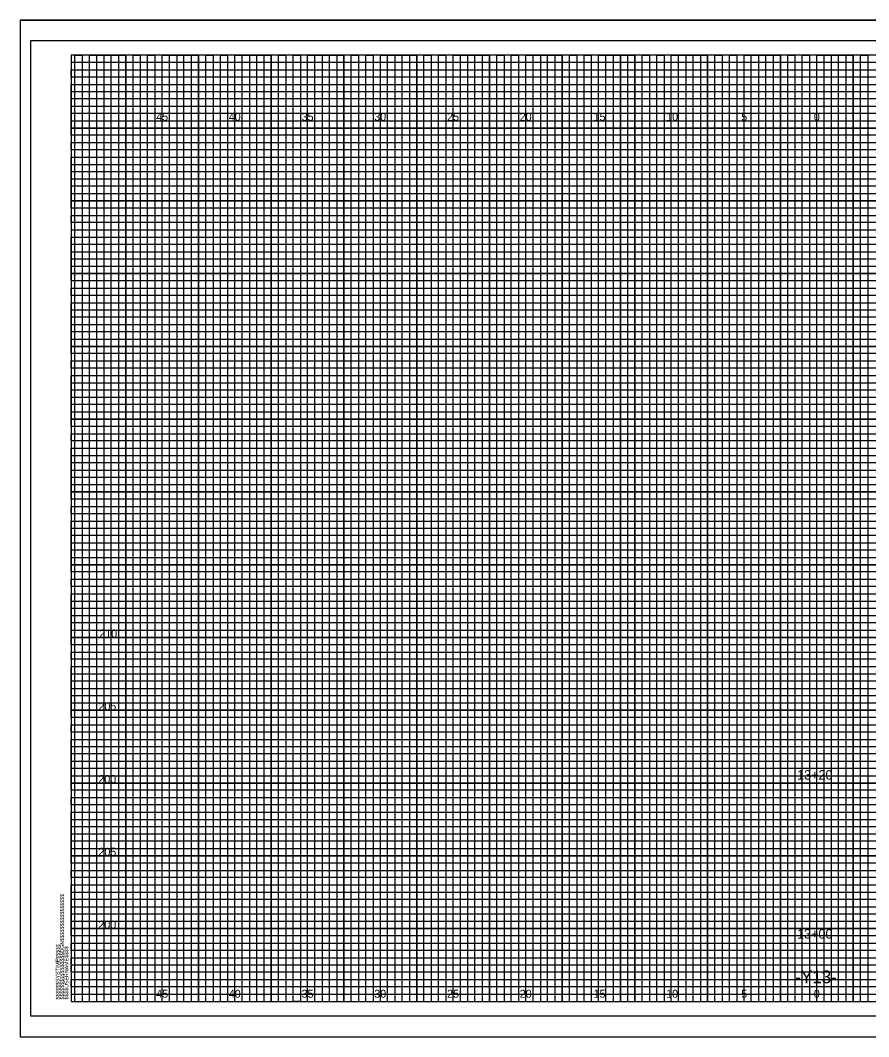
# Model space of a CAD drawing. Extents: x -4 to 103, y -2 to 209.
# Drawn here: x -3.5 to 54.8, y 139.2 to 209.1 of the extents above; entities that cross this region are included whole.
import ezdxf

# ---------------------------------------------------------------- set-up
doc = ezdxf.new("R2010")
doc.units = 0
for name, color, linetype in [('Exist XS Ground Line', 7, 'Continuous'), ('Old_Level_10', 7, 'Continuous'), ('Old_Level_16', 7, 'Continuous'), ('Old_Level_3', 7, 'Continuous'), ('Old_Level_5', 7, 'Continuous'), ('Old_Level_8', 7, 'Continuous'), ('Prop XS Finish Grade Earthwork', 7, 'Continuous'), ('Prop XS Finish Grade Pavement', 7, 'Continuous'), ('Prop XS Pvmt Edge Slope', 7, 'Continuous'), ('Prop XS SE Text', 7, 'Continuous'), ('Prop XS Suitable Common Exc Shape', 7, 'Continuous')]:
    doc.layers.add(name, color=color, linetype=linetype)

msp = doc.modelspace()

# ---------------------------------------------------------------- linework, layer by layer
at = {"layer": 'Exist XS Ground Line'}
msp.add_lwpolyline([(103, 207.65), (-2.8, 207.65), (-2.8, 140.65), (103, 140.65)], close=True, dxfattribs=at)
at = {"layer": 'Old_Level_10'}
for p, q in [((1.25, 141.65), (1.25, 206.65)), ((3.75, 141.65), (3.75, 206.65)), ((6.25, 141.65), (6.25, 206.65)), ((8.75, 141.65), (8.75, 206.65)), ((11.25, 141.65), (11.25, 206.65)), ((13.75, 141.65), (13.75, 206.65)), ((16.25, 141.65), (16.25, 206.65)), ((18.75, 141.65), (18.75, 206.65)), ((21.25, 141.65), (21.25, 206.65)), ((23.75, 141.65), (23.75, 206.65)), ((26.25, 141.65), (26.25, 206.65)), ((28.75, 141.65), (28.75, 206.65)), ((31.25, 141.65), (31.25, 206.65)), ((33.75, 141.65), (33.75, 206.65)), ((36.25, 141.65), (36.25, 206.65)), ((38.75, 141.65), (38.75, 206.65)), ((41.25, 141.65), (41.25, 206.65)), ((43.75, 141.65), (43.75, 206.65)), ((46.25, 141.65), (46.25, 206.65)), ((48.75, 141.65), (48.75, 206.65)), ((51.25, 141.65), (51.25, 206.65)), ((53.75, 141.65), (53.75, 206.65)), ((0, 204.15), (74.25, 204.15)), ((0, 201.65), (102.5, 201.65)), ((0, 199.15), (102.5, 199.15)), ((0, 196.65), (102.5, 196.65)), ((0, 194.15), (102.5, 194.15)), ((0, 191.65), (102.5, 191.65)), ((0, 189.15), (102.5, 189.15)), ((0, 186.65), (102.5, 186.65)), ((0, 184.15), (102.5, 184.15)), ((0, 181.65), (102.5, 181.65)), ((0, 179.15), (102.5, 179.15)), ((0, 176.65), (102.5, 176.65)), ((0, 174.15), (102.5, 174.15)), ((0, 171.65), (102.5, 171.65)), ((0, 169.15), (102.5, 169.15)), ((0, 166.65), (102.5, 166.65)), ((0, 164.15), (102.5, 164.15)), ((0, 161.65), (102.5, 161.65)), ((0, 159.15), (102.5, 159.15)), ((0, 156.65), (102.5, 156.65)), ((0, 154.15), (102.5, 154.15)), ((0, 151.65), (102.5, 151.65)), ((0, 149.15), (102.5, 149.15)), ((0, 146.65), (102.5, 146.65)), ((0, 144.15), (102.5, 144.15))]:
    msp.add_line(p, q, dxfattribs=at)
at = {"layer": 'Old_Level_3'}
for p, q in [((-3.5, 209.05), (103.4, 209.05)), ((-3.5, 209.05), (-3.5, 139.225)), ((-3.5, 139.225), (103.4, 139.225))]:
    msp.add_line(p, q, dxfattribs=at)
at = {"layer": 'Old_Level_5'}
msp.add_lwpolyline([(103.4, 209.05), (-3.5, 209.05), (-3.5, 139.225), (103.4, 139.225)], close=True, dxfattribs=at)
at = {"layer": 'Old_Level_8'}
for points in [[(1.25, 141.65), (1.25, 206.65), (3.75, 206.65), (3.75, 141.65), (6.25, 141.65), (6.25, 206.65), (8.75, 206.65), (8.75, 141.65), (11.25, 141.65), (11.25, 206.65), (13.75, 206.65), (13.75, 141.65), (16.25, 141.65), (16.25, 206.65), (18.75, 206.65), (18.75, 141.65), (21.25, 141.65), (21.25, 206.65), (23.75, 206.65), (23.75, 141.65), (26.25, 141.65), (26.25, 206.65), (28.75, 206.65), (28.75, 141.65), (31.25, 141.65), (31.25, 206.65), (33.75, 206.65), (33.75, 141.65), (36.25, 141.65), (36.25, 206.65), (38.75, 206.65), (38.75, 141.65), (41.25, 141.65), (41.25, 206.65), (43.75, 206.65), (43.75, 141.65), (46.25, 141.65), (46.25, 206.65), (48.75, 206.65), (48.75, 141.65), (51.25, 141.65), (51.25, 206.65), (53.75, 206.65), (53.75, 141.65)], [(102.5, 201.65), (0, 201.65), (0, 204.15), (74.25, 204.15)], [(102.5, 196.65), (0, 196.65), (0, 199.15), (102.5, 199.15)], [(102.5, 191.65), (0, 191.65), (0, 194.15), (102.5, 194.15)], [(102.5, 186.65), (0, 186.65), (0, 189.15), (102.5, 189.15)], [(102.5, 181.65), (0, 181.65), (0, 184.15), (102.5, 184.15)], [(102.5, 176.65), (0, 176.65), (0, 179.15), (102.5, 179.15)], [(102.5, 171.65), (0, 171.65), (0, 174.15), (102.5, 174.15)], [(102.5, 166.65), (0, 166.65), (0, 169.15), (102.5, 169.15)], [(102.5, 161.65), (0, 161.65), (0, 164.15), (102.5, 164.15)], [(102.5, 156.65), (0, 156.65), (0, 159.15), (102.5, 159.15)], [(102.5, 151.65), (0, 151.65), (0, 154.15), (102.5, 154.15)], [(102.5, 146.65), (0, 146.65), (0, 149.15), (102.5, 149.15)], [(0, 144.15), (102.5, 144.15)]]:
    msp.add_lwpolyline(points, dxfattribs=at)
at = {"layer": 'Prop XS Finish Grade Earthwork'}
for points in [[(0, 203.65), (0, 204.65), (74.25, 204.65), (74.25, 205.15), (0, 205.15), (0, 205.65), (74.25, 205.65), (74.25, 206.15), (0, 206.15)], [(0.25, 141.65), (0.25, 206.65), (0.75, 206.65), (0.75, 141.65), (1.75, 141.65), (1.75, 206.65), (2.25, 206.65), (2.25, 141.65), (2.75, 141.65), (2.75, 206.65), (3.25, 206.65), (3.25, 141.65), (4.25, 141.65), (4.25, 206.65), (4.75, 206.65), (4.75, 141.65), (5.25, 141.65), (5.25, 206.65), (5.75, 206.65), (5.75, 141.65), (6.75, 141.65), (6.75, 206.65), (7.25, 206.65), (7.25, 141.65), (7.75, 141.65), (7.75, 206.65), (8.25, 206.65), (8.25, 141.65), (9.25, 141.65), (9.25, 206.65), (9.75, 206.65), (9.75, 141.65), (10.25, 141.65), (10.25, 206.65), (10.75, 206.65), (10.75, 141.65), (11.75, 141.65), (11.75, 206.65), (12.25, 206.65), (12.25, 141.65), (12.75, 141.65), (12.75, 206.65), (13.25, 206.65), (13.25, 141.65), (14.25, 141.65), (14.25, 206.65), (14.75, 206.65), (14.75, 141.65), (15.75, 141.65), (15.25, 141.65), (15.25, 206.65), (15.75, 206.65), (15.75, 141.65), (16.75, 141.65), (16.75, 206.65), (17.25, 206.65), (17.25, 141.65), (17.75, 141.65), (17.75, 206.65), (18.25, 206.65), (18.25, 141.65), (19.25, 141.65), (19.25, 206.65), (19.75, 206.65), (19.75, 141.65), (20.25, 141.65), (20.25, 206.65), (20.75, 206.65), (20.75, 141.65), (21.75, 141.65), (21.75, 206.65), (22.25, 206.65), (22.25, 141.65), (22.75, 141.65), (22.75, 206.65), (23.25, 206.65), (23.25, 141.65), (24.25, 141.65), (24.25, 206.65), (24.75, 206.65), (24.75, 141.65), (25.25, 141.65), (25.25, 206.65), (25.75, 206.65), (25.75, 141.65), (26.75, 141.65), (26.75, 206.65), (27.25, 206.65), (27.25, 141.65), (27.75, 141.65), (27.75, 206.65), (28.25, 206.65), (28.25, 141.65), (29.25, 141.65), (29.25, 206.65), (29.75, 206.65), (29.75, 141.65), (30.25, 141.65), (30.25, 206.65), (30.75, 206.65), (30.75, 141.65)], [(30.75, 141.65), (31.75, 141.65), (31.75, 206.65), (32.25, 206.65), (32.25, 141.65), (32.75, 141.65), (32.75, 206.65), (33.25, 206.65), (33.25, 141.65), (34.25, 141.65), (34.25, 206.65), (34.75, 206.65), (34.75, 141.65), (35.25, 141.65), (35.25, 206.65), (35.75, 206.65), (35.75, 141.65), (36.75, 141.65), (36.75, 206.65), (37.25, 206.65), (37.25, 141.65), (37.75, 141.65), (37.75, 206.65), (37.75, 141.65)], [(38.25, 206.65), (38.25, 141.65), (39.25, 141.65), (39.25, 206.65), (39.75, 206.65), (39.75, 141.65), (40.25, 141.65), (40.25, 206.65), (40.75, 206.65), (40.75, 141.65), (41.75, 141.65), (41.75, 206.65), (42.25, 206.65), (42.25, 141.65), (42.75, 141.65), (42.75, 206.65), (43.25, 206.65), (43.25, 141.65), (43.75, 141.65), (44.25, 141.65), (44.25, 206.65), (44.75, 206.65), (44.75, 141.65), (45.25, 141.65), (45.25, 206.65), (45.75, 206.65), (45.75, 141.65), (46.75, 141.65), (46.75, 206.65), (47.25, 206.65), (47.25, 141.65), (47.75, 141.65), (47.75, 206.65), (48.25, 206.65), (48.25, 141.65), (49.25, 141.65), (49.25, 206.65), (49.75, 206.65), (49.75, 141.65), (50.25, 141.65), (50.25, 206.65), (50.75, 206.65), (50.75, 141.65), (51.75, 141.65), (51.75, 206.65), (52.25, 206.65), (52.25, 141.65), (52.75, 141.65), (52.75, 206.65), (53.25, 206.65), (53.25, 141.65), (54.25, 141.65), (54.25, 206.65), (54.75, 206.65), (54.75, 141.65), (55.25, 141.65)], [(102.5, 203.65), (0, 203.65)], [(102.5, 202.65), (0, 202.65), (0, 203.15), (102.5, 203.15)], [(102.5, 201.15), (0, 201.15), (0, 202.15), (102.5, 202.15)], [(102.5, 200.15), (0, 200.15), (0, 200.65), (102.5, 200.65)], [(102.5, 198.65), (0, 198.65), (0, 199.65), (102.5, 199.65)], [(102.5, 197.65), (0, 197.65), (0, 198.15), (102.5, 198.15)], [(102.5, 196.15), (0, 196.15), (0, 197.15), (102.5, 197.15)], [(102.5, 195.15), (0, 195.15), (0, 195.65), (102.5, 195.65)], [(0, 194.65), (102.5, 194.65)], [(102.5, 193.65), (0, 193.65)], [(102.5, 192.65), (0, 192.65), (0, 193.15), (102.5, 193.15)], [(102.5, 191.15), (0, 191.15), (0, 192.15), (102.5, 192.15)], [(102.5, 190.15), (0, 190.15), (0, 190.65), (102.5, 190.65)], [(102.5, 188.65), (0, 188.65), (0, 189.65), (102.5, 189.65)], [(102.5, 187.65), (0, 187.65), (0, 188.15), (102.5, 188.15)], [(102.5, 186.15), (0, 186.15), (0, 187.15), (102.5, 187.15)], [(102.5, 185.15), (0, 185.15), (0, 185.65), (102.5, 185.65)], [(102.5, 183.65), (0, 183.65), (0, 184.65), (102.5, 184.65)], [(102.5, 182.65), (0, 182.65), (0, 183.15), (102.5, 183.15)], [(102.5, 181.15), (0, 181.15), (0, 182.15), (102.5, 182.15)], [(102.5, 180.15), (0, 180.15), (0, 180.65), (102.5, 180.65)], [(102.5, 178.65), (0, 178.65), (0, 179.65), (102.5, 179.65)], [(102.5, 177.65), (0, 177.65), (0, 178.15), (102.5, 178.15)], [(102.5, 176.15), (0, 176.15), (0, 177.15), (102.5, 177.15)], [(102.5, 175.15), (0, 175.15), (0, 175.65), (102.5, 175.65)], [(102.5, 173.65), (0, 173.65), (0, 174.65), (102.5, 174.65)], [(102.5, 172.65), (0, 172.65), (0, 173.15)], [(0, 173.15), (102.5, 173.15)], [(102.5, 171.15), (0, 171.15), (0, 172.15), (102.5, 172.15)], [(102.5, 170.15), (0, 170.15), (0, 170.65), (102.5, 170.65)], [(102.5, 168.65), (0, 168.65), (0, 169.65), (102.5, 169.65)], [(102.5, 167.65), (0, 167.65), (0, 168.15), (102.5, 168.15)], [(102.5, 166.15), (0, 166.15), (0, 167.15), (102.5, 167.15)], [(102.5, 165.15), (0, 165.15), (0, 165.65), (102.5, 165.65)], [(102.5, 163.65), (0, 163.65), (0, 164.65), (102.5, 164.65)], [(102.5, 162.65), (0, 162.65), (0, 163.15), (102.5, 163.15)], [(102.5, 161.15), (0, 161.15), (0, 162.15), (102.5, 162.15)], [(102.5, 160.15), (0, 160.15), (0, 160.65), (102.5, 160.65)], [(102.5, 158.65), (0, 158.65), (0, 159.65), (102.5, 159.65)], [(102.5, 157.65), (0, 157.65), (0, 158.15), (102.5, 158.15)], [(102.5, 156.15), (0, 156.15), (0, 157.15), (102.5, 157.15)], [(102.5, 155.15), (0, 155.15), (0, 155.65), (102.5, 155.65)], [(102.5, 153.65), (0, 153.65), (0, 154.65), (102.5, 154.65)], [(102.5, 152.65), (0, 152.65), (0, 153.15), (102.5, 153.15)], [(102.5, 151.15), (0, 151.15), (0, 152.15), (102.5, 152.15)], [(102.5, 150.15), (0, 150.15), (0, 150.65), (102.5, 150.65)], [(102.5, 148.65), (0, 148.65), (0, 149.65), (102.5, 149.65)], [(102.5, 147.65), (0, 147.65), (0, 148.15), (102.5, 148.15)], [(102.5, 146.15), (0, 146.15), (0, 147.15), (102.5, 147.15)], [(102.5, 145.15), (0, 145.15), (0, 145.65), (102.5, 145.65)], [(102.5, 143.65), (0, 143.65), (0, 144.65), (102.5, 144.65)], [(102.5, 142.65), (0, 142.65), (0, 143.15), (102.5, 143.15)], [(0, 142.15), (102.5, 142.15)]]:
    msp.add_lwpolyline(points, dxfattribs=at)
at = {"layer": 'Prop XS SE Text'}
msp.add_lwpolyline([(102.5, 206.65), (0, 206.65), (0, 141.65), (102.5, 141.65)], close=True, dxfattribs=at)

# ---------------------------------------------------------------- texts
at = {"layer": 'Old_Level_16'}
for s, p in [('45', (5.84, 202.15)), ('40', (10.831, 202.15)), ('35', (15.84, 202.15)), ('30', (20.831, 202.15)), ('25', (25.84, 202.15)), ('20', (30.831, 202.15)), ('15', (35.906, 202.15)), ('10', (40.897, 202.15)), ('5', (46.057, 202.15)), ('0', (51.049, 202.15)), ('0', (51.049, 202.15)), ('45', (5.84, 141.9)), ('40', (10.831, 141.9)), ('35', (15.84, 141.9)), ('30', (20.831, 141.9)), ('25', (25.84, 141.9)), ('20', (30.831, 141.9)), ('15', (35.906, 141.9)), ('10', (40.897, 141.9)), ('5', (46.057, 141.9)), ('0', (51.049, 141.9)), ('0', (51.049, 141.9))]:
    msp.add_text(s, height=0.55, dxfattribs=at).set_placement(p)
at = {"layer": 'Old_Level_8'}
msp.add_text('040397', height=0.0025, rotation=90, dxfattribs=at).set_placement((-0.001, 206.636))
at = {"layer": 'Prop XS Finish Grade Pavement'}
for s, p in [('210', (1.93, 166.65)), ('205', (1.872, 161.65)), ('200', (1.864, 156.65)), ('205', (1.872, 151.65)), ('200', (1.864, 146.65))]:
    msp.add_text(s, height=0.55, dxfattribs=at).set_placement(p)
at = {"layer": 'Prop XS Pvmt Edge Slope'}
msp.add_text('-Y13-', height=0.875, dxfattribs=at).set_placement((49.773, 142.9))
at = {"layer": 'Prop XS SE Text'}
for s, p in [('$$$$$$$$$$$$$$$$DGN$$$$$$$$$$$$$$$$', (-0.5, 141.775)), ('$$$$$$SYSTIME$$$$$', (-0.797, 141.775)), ('$$$$USERNAME$$$$', (-0.2, 141.775))]:
    msp.add_text(s, height=0.2625, rotation=90, dxfattribs=at).set_placement(p)
at = {"layer": 'Prop XS Suitable Common Exc Shape'}
for s, p in [('13+20', (49.893, 156.885)), ('13+00', (49.893, 145.961))]:
    msp.add_text(s, height=0.65, dxfattribs=at).set_placement(p)

doc.saveas('drawing.dxf')
